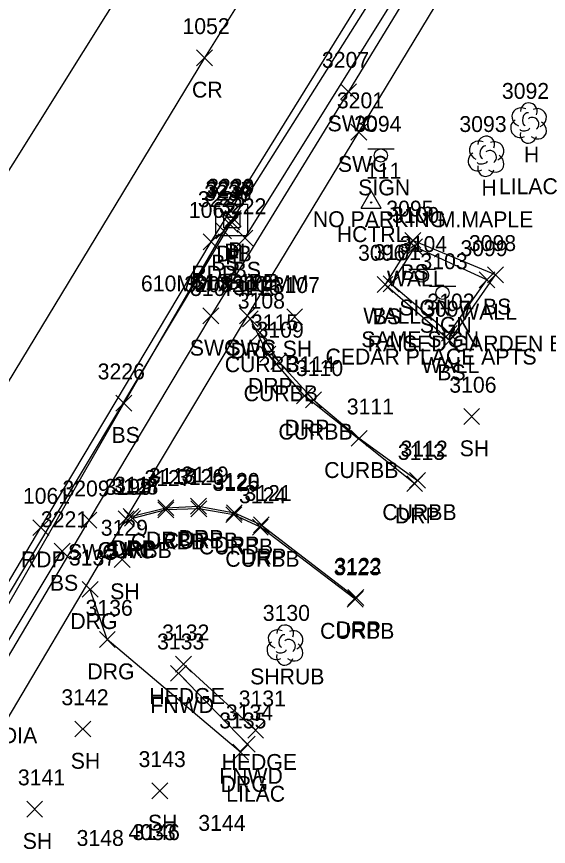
# Model space of a CAD drawing. Extents: x 1634209 to 1639641, y 608564 to 612258.
# Drawn here: x 1638954.2 to 1639021.2, y 610938 to 611042.5 of the extents above; entities that cross this region are included whole.
import ezdxf

# ---------------------------------------------------------------- set-up
doc = ezdxf.new("R2010")
doc.units = 0
for name, color, linetype in [('C_A', 7, 'Continuous'), ('C_I', 7, 'Continuous'), ('CPH', 7, 'Continuous'), ('D_A', 7, 'Continuous'), ('D_C', 7, 'Continuous'), ('D_I', 7, 'Continuous'), ('D_TIC', 7, 'Continuous'), ('DCP', 7, 'Continuous'), ('DS', 7, 'Continuous'), ('L_A', 7, 'Continuous'), ('L_C', 7, 'Continuous'), ('L_I', 7, 'Continuous'), ('L_TIC', 7, 'Continuous'), ('LAHR', 7, 'Continuous'), ('LELB', 7, 'Continuous'), ('LFNC', 7, 'Continuous'), ('LSH', 7, 'Continuous'), ('LTD', 7, 'Continuous'), ('LW', 7, 'Continuous'), ('P_A', 7, 'Continuous'), ('P_I', 7, 'Continuous'), ('P_TIC', 7, 'Continuous'), ('PET', 7, 'Continuous'), ('PRC', 7, 'Continuous'), ('R_A', 7, 'Continuous'), ('R_I', 7, 'Continuous'), ('R_TIC', 7, 'Continuous'), ('RC', 7, 'Continuous'), ('RDG', 7, 'Continuous'), ('RDP', 7, 'Continuous'), ('RSW', 7, 'Continuous'), ('S_A', 7, 'Continuous'), ('S_C', 7, 'Continuous'), ('S_I', 7, 'Continuous'), ('SSGN', 7, 'Continuous'), ('U_C', 7, 'Continuous')]:
    doc.layers.add(name, color=color, linetype=linetype)

msp = doc.modelspace()

# ---------------------------------------------------------------- linework, layer by layer
at = {"layer": 'CPH'}
for p, q in [((1638997.64, 611018.35), (1638998.89, 611020.51)), ((1639000.14, 611018.35), (1638998.89, 611020.51)), ((1638998.89, 611019.07), (1638998.89, 611019.07)), ((1638997.64, 611018.35), (1639000.14, 611018.35))]:
    msp.add_line(p, q, dxfattribs=at)
msp.add_circle((1638998.89, 611019.07), 0.0833, dxfattribs=at)
at = {"layer": 'D_TIC'}
for points in [[(1638980.5, 611016.05), (1638982.5, 611018.05)], [(1638982.5, 611016.05), (1638980.5, 611018.05)], [(1638980.11, 611015.29), (1638982.11, 611017.29)], [(1638982.11, 611015.29), (1638980.11, 611017.29)], [(1638980.28, 611015.63), (1638982.28, 611017.63)], [(1638982.28, 611015.63), (1638980.28, 611017.63)]]:
    msp.add_lwpolyline(points, dxfattribs=at)
at = {"layer": 'DCP'}
for points in [[(1638981.5, 611017.05), (1639053.43, 611130.86)], [(1638930.73, 610932.22), (1638981.11, 611016.29)]]:
    msp.add_lwpolyline(points, dxfattribs=at)
at = {"layer": 'DS'}
for p, q in [((1638979.32, 611018.87), (1638983.32, 611018.87)), ((1638979.32, 611014.87), (1638979.32, 611018.87)), ((1638980.32, 611015.87), (1638980.32, 611017.87)), ((1638980.32, 611017.87), (1638982.32, 611017.87)), ((1638982.32, 611017.87), (1638982.32, 611015.87)), ((1638983.32, 611018.87), (1638983.32, 611014.87)), ((1638981.33, 611016.87), (1638981.33, 611016.87)), ((1638981.33, 611016.87), (1638981.33, 611016.87)), ((1638982.32, 611015.87), (1638980.32, 611015.87)), ((1638983.32, 611014.87), (1638979.32, 611014.87))]:
    msp.add_line(p, q, dxfattribs=at)
at = {"layer": 'L_TIC'}
for points in [[(1638979.31, 611014.48), (1638981.31, 611016.48)], [(1638981.31, 611014.48), (1638979.31, 611016.48)], [(1638981.99, 611013.59), (1638983.99, 611015.59)], [(1638983.99, 611013.59), (1638981.99, 611015.59)], [(1639003.14, 611013.29), (1639005.14, 611015.29)], [(1639005.14, 611013.29), (1639003.14, 611015.29)], [(1639003.38, 611012.49), (1639005.38, 611014.49)], [(1639005.38, 611012.49), (1639003.38, 611014.49)], [(1639013.55, 611008.95), (1639015.55, 611010.95)], [(1639015.55, 611008.95), (1639013.55, 611010.95)], [(1638999.64, 611007.73), (1639001.64, 611009.73)], [(1639001.64, 611007.73), (1638999.64, 611009.73)], [(1639000.42, 611007.81), (1639002.42, 611009.81)], [(1639002.42, 611007.81), (1639000.42, 611009.81)], [(1639012.49, 611008.31), (1639014.49, 611010.31)], [(1639014.49, 611008.31), (1639012.49, 611010.31)], [(1638988.25, 611003.66), (1638990.25, 611005.66)], [(1638990.25, 611003.66), (1638988.25, 611005.66)], [(1639007.74, 611001.59), (1639009.74, 611003.59)], [(1639009.74, 611001.59), (1639007.74, 611003.59)], [(1639007.79, 611000.68), (1639009.79, 611002.68)], [(1639009.79, 611000.68), (1639007.79, 611002.68)], [(1638966.73, 610992.79), (1638968.73, 610994.79)], [(1638968.73, 610992.79), (1638966.73, 610994.79)], [(1639010.56, 610991.11), (1639012.56, 610993.11)], [(1639012.56, 610991.11), (1639010.56, 610993.11)], [(1638958.96, 610974.17), (1638960.96, 610976.17)], [(1638960.96, 610974.17), (1638958.96, 610976.17)], [(1638966.51, 610973.1), (1638968.51, 610975.1)], [(1638968.51, 610973.1), (1638966.51, 610975.1)], [(1638974.24, 610959.92), (1638976.24, 610961.92)], [(1638976.24, 610959.92), (1638974.24, 610961.92)], [(1638973.61, 610958.78), (1638975.61, 610960.78)], [(1638975.61, 610958.78), (1638973.61, 610960.78)], [(1638961.55, 610951.76), (1638963.55, 610953.76)], [(1638963.55, 610951.76), (1638961.55, 610953.76)], [(1638983.33, 610951.61), (1638985.33, 610953.61)], [(1638985.33, 610951.61), (1638983.33, 610953.61)], [(1638982.28, 610949.86), (1638984.28, 610951.86)], [(1638984.28, 610949.86), (1638982.28, 610951.86)], [(1638971.27, 610943.97), (1638973.27, 610945.97)], [(1638973.27, 610943.97), (1638971.27, 610945.97)], [(1638955.49, 610941.67), (1638957.49, 610943.67)], [(1638957.49, 610941.67), (1638955.49, 610943.67)]]:
    msp.add_lwpolyline(points, dxfattribs=at)
at = {"layer": 'LAHR'}
msp.add_lwpolyline([(1638984.33, 610952.61), (1638975.24, 610960.92)], dxfattribs=at)
at = {"layer": 'LELB'}
for points in [[(1638982.99, 611014.59), (1639013.75, 611063.89), (1639039.18, 611103.98)], [(1638980.31, 611015.48), (1638967.73, 610993.79), (1638947.97, 610959.55), (1638931.37, 610930.97), (1638912.43, 610898.55), (1638893.71, 610864.41), (1638879.66, 610839.16)], [(1639004.14, 611014.29), (1639000.64, 611008.73), (1639008.79, 611001.68), (1639014.55, 611009.95)], [(1639014.55, 611009.95), (1639004.14, 611014.29)], [(1638882.82, 610837.01), (1638905.5, 610879.25), (1638921.2, 610907.42), (1638935.13, 610933.84), (1638959.96, 610975.17)]]:
    msp.add_lwpolyline(points, dxfattribs=at)
at = {"layer": 'LFNC'}
msp.add_lwpolyline([(1638974.61, 610959.78), (1638983.28, 610950.86)], dxfattribs=at)
at = {"layer": 'LSH'}
msp.add_line((1638988.01, 610963.38), (1638988.01, 610963.38), dxfattribs=at)
msp.add_line((1638988.01, 610963.38), (1638988.01, 610963.38), dxfattribs=at)
msp.add_arc((1638988.05, 610964.81), 1.05, 335.5272, 180.9563, dxfattribs=at)
for centre, major_axis, ratio, start_param, end_param in [((1638987.21, 610964.05), (1.21, -0.51), 0.895232, 1.570796, 4.712389), ((1638987.8, 610963.84), (-0.208, -0.792), 0.645439, 3.141593, 6.283185), ((1638989.05, 610963.96), (-1.14, -0.48), 0.949671, 1.570796, 4.712389), ((1638986.92, 610962.67), (0.58, -1.04), 0.959034, 3.141593, 6.283185), ((1638988.51, 610963.21), (-0.5, 0.667), 0.989748, 3.141593, 6.283185), ((1638987.55, 610962.63), (-0.625, -0.083), 0.423636, 0, 3.141593), ((1638989.01, 610962.55), (-1.09, 0.79), 0.841452, 1.570796, 4.712389), ((1638988.01, 610961.88), (0.26, 1.06), 0.942809, 1.570796, 4.712389)]:
    msp.add_ellipse(centre, major_axis=major_axis, ratio=ratio, start_param=start_param, end_param=end_param, dxfattribs=at)
at = {"layer": 'LTD'}
for p, q in [((1639018.71, 611029.11), (1639018.71, 611029.11)), ((1639018.71, 611029.11), (1639018.71, 611029.11)), ((1639013.35, 611024.94), (1639013.35, 611024.94)), ((1639013.35, 611024.94), (1639013.35, 611024.94))]:
    msp.add_line(p, q, dxfattribs=at)
for centre in [(1639018.76, 611030.55), (1639013.4, 611026.37)]:
    msp.add_arc(centre, 1.05, 335.5272, 180.9563, dxfattribs=at)
for centre, major_axis, ratio, start_param, end_param in [((1639017.92, 611029.78), (1.21, -0.51), 0.895232, 1.570796, 4.712389), ((1639018.5, 611029.57), (-0.208, -0.792), 0.645439, 3.141593, 6.283185), ((1639019.75, 611029.7), (-1.14, -0.48), 0.949671, 1.570796, 4.712389), ((1639017.63, 611028.41), (0.58, -1.04), 0.959034, 3.141593, 6.283185), ((1639019.21, 611028.95), (-0.5, 0.667), 0.989748, 3.141593, 6.283185), ((1639018.25, 611028.36), (-0.625, -0.083), 0.423636, 0, 3.141593), ((1639019.71, 611028.28), (-1.09, 0.79), 0.841452, 1.570796, 4.712389), ((1639018.71, 611027.61), (0.26, 1.06), 0.942809, 1.570796, 4.712389), ((1639012.56, 611025.6), (1.21, -0.51), 0.895232, 1.570796, 4.712389), ((1639013.14, 611025.39), (-0.208, -0.792), 0.645439, 3.141593, 6.283185), ((1639014.39, 611025.52), (-1.14, -0.48), 0.949671, 1.570796, 4.712389), ((1639012.27, 611024.23), (0.58, -1.04), 0.959034, 3.141593, 6.283185), ((1639013.85, 611024.77), (-0.5, 0.667), 0.989748, 3.141593, 6.283185), ((1639012.89, 611024.19), (-0.625, -0.083), 0.423636, 0, 3.141593), ((1639014.35, 611024.1), (-1.09, 0.79), 0.841452, 1.570796, 4.712389), ((1639013.35, 611023.44), (0.26, 1.06), 0.942809, 1.570796, 4.712389)]:
    msp.add_ellipse(centre, major_axis=major_axis, ratio=ratio, start_param=start_param, end_param=end_param, dxfattribs=at)
at = {"layer": 'LW'}
for points in [[(1639013.49, 611009.31), (1639004.38, 611013.49), (1639001.42, 611008.81), (1639008.74, 611002.59)], [(1639008.74, 611002.59), (1639013.49, 611009.31)]]:
    msp.add_lwpolyline(points, dxfattribs=at)
at = {"layer": 'P_TIC'}
for points in [[(1638976.88, 611036.27), (1638978.88, 611038.27)], [(1638978.88, 611036.27), (1638976.88, 611038.27)], [(1638977.73, 611013.12), (1638979.73, 611015.12)], [(1638979.73, 611013.12), (1638977.73, 611015.12)], [(1638956.25, 610977.12), (1638958.25, 610979.12)], [(1638958.25, 610977.12), (1638956.25, 610979.12)]]:
    msp.add_lwpolyline(points, dxfattribs=at)
at = {"layer": 'PET'}
for points in [[(1638854.83, 610853.22), (1638885.37, 610909), (1638902.82, 610937.28), (1638929.33, 610982.56), (1638950.92, 611019.42), (1638971.29, 611051.92), (1639000.04, 611096.96), (1639023.57, 611133.7), (1639039.12, 611159.19), (1639064.62, 611197.78), (1639080.51, 611223.3), (1639114.23, 611277.34), (1639131.17, 611302.28), (1639149.64, 611331.79), (1639176.42, 611372.35), (1639193.48, 611398.88), (1639220.96, 611441.47), (1639247.22, 611483.75)], [(1638878.4, 610839.82), (1638902.26, 610883.1), (1638925.76, 610925.06), (1638957.25, 610978.12), (1638978.73, 611014.12), (1639004.29, 611055.32), (1639040.97, 611112.28), (1639073.41, 611162.89), (1639072.72, 611163.46), (1639102.57, 611207.56), (1639124.27, 611240.99), (1639140.69, 611264.29), (1639156.2, 611287.4), (1639175.63, 611318.1), (1639189.77, 611341.61), (1639219.88, 611389.38), (1639245.26, 611428.04), (1639265.27, 611462.65)]]:
    msp.add_lwpolyline(points, dxfattribs=at)
at = {"layer": 'PRC'}
msp.add_lwpolyline([(1639250.46, 611462.84), (1639222.36, 611418.18), (1639195.34, 611376.28), (1639169.71, 611336.75), (1639147.17, 611302.78), (1639120.59, 611261.16), (1639092.55, 611217.83), (1639063.71, 611172.41), (1639032.46, 611123.7), (1639004.79, 611080.3), (1638977.88, 611037.27), (1638950.44, 610992.13), (1638925.96, 610950.29), (1638900.29, 610905.36), (1638879.75, 610869.2), (1638867.15, 610846.08)], dxfattribs=at)
at = {"layer": 'R_TIC'}
for points in [[(1638995.03, 611032.02), (1638997.03, 611034.02)], [(1638997.03, 611032.02), (1638995.03, 611034.02)], [(1638996.34, 611026.92), (1638998.34, 611028.92)], [(1638998.34, 611026.92), (1638996.34, 611028.92)], [(1638977.68, 611003.78), (1638979.68, 611005.78)], [(1638979.68, 611003.78), (1638977.68, 611005.78)], [(1638982.29, 611003.79), (1638984.29, 611005.79)], [(1638984.29, 611003.79), (1638982.29, 611005.79)], [(1638982.67, 611003.4), (1638984.67, 611005.4)], [(1638984.67, 611003.4), (1638982.67, 611005.4)], [(1638983.85, 611001.7), (1638985.85, 611003.7)], [(1638985.85, 611001.7), (1638983.85, 611003.7)], [(1638984.86, 610998.97), (1638986.86, 611000.97)], [(1638986.86, 610998.97), (1638984.86, 611000.97)], [(1638986.23, 610998.04), (1638988.23, 611000.04)], [(1638988.23, 610998.04), (1638986.23, 611000.04)], [(1638989.48, 610993.71), (1638991.48, 610995.71)], [(1638991.48, 610993.71), (1638989.48, 610995.71)], [(1638990.62, 610993.21), (1638992.62, 610995.21)], [(1638992.62, 610993.21), (1638990.62, 610995.21)], [(1638996.38, 610988.37), (1638998.38, 610990.37)], [(1638998.38, 610988.37), (1638996.38, 610990.37)], [(1639003.38, 610982.65), (1639005.38, 610984.65)], [(1639005.38, 610982.65), (1639003.38, 610984.65)], [(1639003.72, 610983.07), (1639005.72, 610985.07)], [(1639005.72, 610983.07), (1639003.72, 610985.07)], [(1638972.01, 610979.63), (1638974.01, 610981.63)], [(1638974.01, 610979.63), (1638972.01, 610981.63)], [(1638972.01, 610979.37), (1638974.01, 610981.37)], [(1638974.01, 610979.37), (1638972.01, 610981.37)], [(1638976.13, 610979.81), (1638978.13, 610981.81)], [(1638978.13, 610979.81), (1638976.13, 610981.81)], [(1638976.17, 610979.5), (1638978.17, 610981.5)], [(1638978.17, 610979.5), (1638976.17, 610981.5)], [(1638967.01, 610978.25), (1638969.01, 610980.25)], [(1638969.01, 610978.25), (1638967.01, 610980.25)], [(1638967.62, 610978.53), (1638969.62, 610980.53)], [(1638969.62, 610978.53), (1638967.62, 610980.53)], [(1638967.82, 610978.29), (1638969.82, 610980.29)], [(1638969.82, 610978.29), (1638967.82, 610980.29)], [(1638980.59, 610978.75), (1638982.59, 610980.75)], [(1638982.59, 610978.75), (1638980.59, 610980.75)], [(1638980.65, 610979), (1638982.65, 610981)], [(1638982.65, 610979), (1638980.65, 610981)], [(1638962.33, 610978.05), (1638964.33, 610980.05)], [(1638964.33, 610978.05), (1638962.33, 610980.05)], [(1638984.05, 610977.48), (1638986.05, 610979.48)], [(1638986.05, 610977.48), (1638984.05, 610979.48)], [(1638983.93, 610977.19), (1638985.93, 610979.19)], [(1638985.93, 610977.19), (1638983.93, 610979.19)], [(1638962.49, 610969.35), (1638964.49, 610971.35)], [(1638964.49, 610969.35), (1638962.49, 610971.35)], [(1638995.87, 610968.12), (1638997.87, 610970.12)], [(1638997.87, 610968.12), (1638995.87, 610970.12)], [(1638995.96, 610968.31), (1638997.96, 610970.31)], [(1638997.96, 610968.31), (1638995.96, 610970.31)], [(1638964.64, 610963.02), (1638966.64, 610965.02)], [(1638966.64, 610963.02), (1638964.64, 610965.02)], [(1638981.44, 610948.84), (1638983.44, 610950.84)], [(1638983.44, 610948.84), (1638981.44, 610950.84)]]:
    msp.add_lwpolyline(points, dxfattribs=at)
at = {"layer": 'RC'}
for points in [[(1638984.85, 611002.7), (1638987.23, 610999.04), (1638991.62, 610994.21), (1638997.38, 610989.37), (1639004.72, 610984.07)], [(1638996.87, 610969.12), (1638984.93, 610978.19), (1638981.59, 610979.75), (1638977.17, 610980.5), (1638973.01, 610980.37), (1638968.82, 610979.29)]]:
    msp.add_lwpolyline(points, dxfattribs=at)
at = {"layer": 'RDG'}
msp.add_lwpolyline([(1638982.44, 610949.84), (1638965.64, 610964.02), (1638963.49, 610970.35)], dxfattribs=at)
at = {"layer": 'RDP'}
for points in [[(1639004.38, 610983.65), (1638990.48, 610994.71), (1638985.86, 610999.97), (1638983.67, 611004.4)], [(1638968.62, 610979.53), (1638973.01, 610980.63), (1638977.13, 610980.81), (1638981.65, 610980), (1638985.05, 610978.48), (1638996.96, 610969.31)]]:
    msp.add_lwpolyline(points, dxfattribs=at)
at = {"layer": 'RSW'}
for points in [[(1639042.52, 611106.87), (1639016.95, 611067.31), (1638996.03, 611033.02), (1638978.68, 611004.78), (1638963.33, 610979.05), (1638946.23, 610950.27), (1638931.64, 610924.09), (1638919.4, 610902.22), (1638904.83, 610875.98), (1638895.3, 610858.44), (1638883.54, 610836.57)], [(1638887.24, 610836.54), (1638902.8, 610864.3), (1638908.08, 610874.62), (1638910.81, 610879.12), (1638923.92, 610902.1), (1638938.05, 610928.02), (1638949.86, 610948.73), (1638968.01, 610979.25), (1638983.29, 611004.79), (1638997.34, 611027.92), (1639015.73, 611058.3), (1639044.74, 611103.21)]]:
    msp.add_lwpolyline(points, dxfattribs=at)
at = {"layer": 'SSGN'}
for p, q in [((1638998.47, 611025.82), (1639001.8, 611025.82)), ((1639000.12, 611024.98), (1639000.12, 611024.98)), ((1639003.66, 611010.68), (1639006.99, 611010.68)), ((1639005.3, 611009.85), (1639005.3, 611009.85)), ((1639006.24, 611008.52), (1639009.57, 611008.52)), ((1639007.89, 611007.68), (1639007.89, 611007.68))]:
    msp.add_line(p, q, dxfattribs=at)
for centre in [(1639000.12, 611024.98), (1639005.3, 611009.85), (1639007.89, 611007.68)]:
    msp.add_circle(centre, 0.833, dxfattribs=at)

# ---------------------------------------------------------------- texts
at = {"layer": 'C_A'}
msp.add_text('HCTRL', height=2, dxfattribs=at).set_placement((1638994.56, 611014.07))
at = {"layer": 'C_I'}
for s, p in [('111', (1638998.23, 611022.07)), ('4033', (1638968.31, 610938.77))]:
    msp.add_text(s, height=2, dxfattribs=at).set_placement(p)
at = {"layer": 'D_A'}
for s, p in [('DI', (1638980.38, 611011.87)), ('P', (1638980.88, 611012.05)), ('DIB', (1638979.38, 611011.63)), ('P', (1638980.49, 611011.29))]:
    msp.add_text(s, height=2, dxfattribs=at).set_placement(p)
at = {"layer": 'D_C'}
for s, p in [('610MM X 610MM', (1638969.88, 611007.87)), ('310PIPE', (1638976.46, 611008.05)), ('310PIPE', (1638976.07, 611007.29))]:
    msp.add_text(s, height=2, dxfattribs=at).set_placement(p)
at = {"layer": 'D_I'}
for s, p in [('3239', (1638978.23, 611020.05)), ('3238', (1638977.85, 611019.29)), ('3236', (1638978.01, 611019.87)), ('3237', (1638978.02, 611019.63))]:
    msp.add_text(s, height=2, dxfattribs=at).set_placement(p)
at = {"layer": 'L_A'}
for s, p in [('H', (1639018.14, 611024.11)), ('H', (1639012.79, 611019.94)), ('BS', (1638978.75, 611010.48)), ('BS', (1638981.43, 611009.59)), ('BS', (1639002.58, 611009.29)), ('WALL', (1639000.87, 611008.49)), ('BS', (1639012.99, 611004.95)), ('WALL', (1638997.9, 611003.81)), ('BS', (1638999.08, 611003.73)), ('WALL', (1639009.98, 611004.31)), ('SH', (1638987.74, 610999.66)), ('WALL', (1639005.23, 610997.59)), ('BS', (1639007.23, 610996.68)), ('BS', (1638966.17, 610988.79)), ('SH', (1639010.05, 610987.11)), ('BS', (1638958.4, 610970.17)), ('SH', (1638966, 610969.1)), ('SHRUB', (1638983.64, 610958.38)), ('HEDGE', (1638970.94, 610955.92)), ('FNWD', (1638971.07, 610954.78)), ('SH', (1638961.03, 610947.76)), ('HEDGE', (1638980.03, 610947.61)), ('FNWD', (1638979.74, 610945.86)), ('SH', (1638970.76, 610939.97)), ('SH', (1638954.98, 610937.67))]:
    msp.add_text(s, height=2, dxfattribs=at).set_placement(p)
at = {"layer": 'L_C'}
for s, p in [('LILAC', (1639014.98, 611020.11)), ('M.MAPLE', (1639007.29, 611015.94)), ('RAISED GARDEN BED', (1638998.44, 611000.31)), ('LILAC', (1638980.61, 610943.61))]:
    msp.add_text(s, height=2, dxfattribs=at).set_placement(p)
at = {"layer": 'L_I'}
for s, p in [('3092', (1639015.37, 611032.11)), ('3093', (1639010.01, 611027.94)), ('3225', (1638977.05, 611018.48)), ('3222', (1638979.73, 611017.59)), ('3095', (1639000.8, 611017.29)), ('3100', (1639001.52, 611016.49)), ('3098', (1639011.21, 611012.95)), ('3096', (1638997.24, 611011.73)), ('3101', (1638999.21, 611011.81)), ('3099', (1639010.14, 611012.31)), ('3107', (1638986.48, 611007.66)), ('3102', (1639005.97, 611005.59)), ('3097', (1639005.45, 611004.68)), ('3226', (1638964.42, 610996.79)), ('3106', (1639008.74, 610995.11)), ('3221', (1638957.27, 610978.17)), ('3129', (1638964.81, 610977.1)), ('3130', (1638985.23, 610966.38)), ('3132', (1638972.55, 610963.92)), ('3133', (1638971.91, 610962.78)), ('3142', (1638959.85, 610955.76)), ('3131', (1638982.2, 610955.61)), ('3134', (1638980.58, 610953.86)), ('3143', (1638969.58, 610947.97)), ('3141', (1638954.37, 610945.67)), ('3144', (1638977.11, 610939.94)), ('3146', (1638968.83, 610938.78)), ('3148', (1638961.77, 610938.04))]:
    msp.add_text(s, height=2, dxfattribs=at).set_placement(p)
at = {"layer": 'P_A'}
for s, p in [('CR', (1638976.31, 611032.27)), ('RDP', (1638976.22, 611009.12)), ('RDP', (1638954.74, 610973.12))]:
    msp.add_text(s, height=2, dxfattribs=at).set_placement(p)
at = {"layer": 'P_I'}
for s, p in [('1052', (1638975.11, 611040.27)), ('1062', (1638975.91, 611017.12)), ('1061', (1638955, 610981.12))]:
    msp.add_text(s, height=2, dxfattribs=at).set_placement(p)
at = {"layer": 'R_A'}
for s, p in [('SWC', (1638993.4, 611028.02)), ('SWC', (1638994.7, 611022.92)), ('SWC', (1638976.04, 610999.78)), ('SWC', (1638980.65, 610999.79)), ('DRP', (1638981.16, 610999.4)), ('CURBB', (1638980.44, 610997.7)), ('DRP', (1638983.35, 610994.97)), ('CURBB', (1638982.82, 610994.04)), ('CURBB', (1638987.2, 610989.21)), ('DRP', (1638987.97, 610989.71)), ('CURBB', (1638992.97, 610984.37)), ('CURBB', (1639000.3, 610979.07)), ('DRP', (1639001.87, 610978.65)), ('CURBB', (1638968.59, 610975.37)), ('DRP', (1638970.5, 610975.63)), ('CURBB', (1638972.75, 610975.5)), ('DRP', (1638974.61, 610975.81)), ('SWC', (1638960.69, 610974.05)), ('CURBB', (1638964.41, 610974.29)), ('SWC', (1638965.37, 610974.25)), ('DRP', (1638966.11, 610974.53)), ('CURBB', (1638977.17, 610974.75)), ('DRP', (1638979.14, 610975)), ('CURBB', (1638980.51, 610973.19)), ('DRP', (1638982.54, 610973.48)), ('DRG', (1638960.98, 610965.35)), ('CURBB', (1638992.45, 610964.12)), ('DRP', (1638994.45, 610964.31)), ('DRG', (1638963.13, 610959.02)), ('DRG', (1638979.92, 610944.84))]:
    msp.add_text(s, height=2, dxfattribs=at).set_placement(p)
at = {"layer": 'R_I'}
for s, p in [('3207', (1638992.69, 611036.02)), ('3201', (1638994.57, 611030.92)), ('3208', (1638975.34, 611007.78)), ('3200', (1638979.86, 611007.79)), ('3116', (1638981.49, 611007.4)), ('3108', (1638982.08, 611005.7)), ('3115', (1638983.74, 611002.97)), ('3109', (1638984.45, 611002.04)), ('3114', (1638988.36, 610997.71)), ('3110', (1638989.41, 610997.21)), ('3111', (1638995.82, 610992.37)), ('3113', (1639002.25, 610986.65)), ('3112', (1639002.59, 610987.07)), ('3118', (1638970.88, 610983.63)), ('3126', (1638974.42, 610983.5)), ('3119', (1638974.99, 610983.81)), ('3117', (1638966.49, 610982.53)), ('3127', (1638970.32, 610983.37)), ('3120', (1638978.87, 610983)), ('3125', (1638978.9, 610982.75)), ('3209', (1638959.98, 610982.05)), ('3199', (1638965.31, 610982.25)), ('3128', (1638966.13, 610982.29)), ('3121', (1638982.92, 610981.48)), ('3124', (1638982.24, 610981.19)), ('3137', (1638960.8, 610973.35)), ('3123', (1638994.17, 610972.12)), ('3122', (1638994.27, 610972.31)), ('3136', (1638962.9, 610967.02)), ('3135', (1638979.74, 610952.84))]:
    msp.add_text(s, height=2, dxfattribs=at).set_placement(p)
at = {"layer": 'S_A'}
for p in [(1638997.26, 611019.96), (1639002.44, 611004.83), (1639005.03, 611002.66)]:
    msp.add_text('SIGN', height=2, dxfattribs=at).set_placement(p)
at = {"layer": 'S_C'}
for s, p in [('NO PARKING', (1638991.54, 611015.96)), ('SAME SIGN', (1638997.65, 611000.83)), ('CEDAR PLACE APTS', (1638993.14, 610998.66))]:
    msp.add_text(s, height=2, dxfattribs=at).set_placement(p)
at = {"layer": 'S_I'}
for s, p in [('3094', (1638996.76, 611027.96)), ('3104', (1639002.51, 611012.83)), ('3103', (1639005.1, 611010.66))]:
    msp.add_text(s, height=2, dxfattribs=at).set_placement(p)
at = {"layer": 'U_C'}
msp.add_text('660MM DIA', height=2, dxfattribs=at).set_placement((1638942.69, 610950.96))

doc.saveas('drawing.dxf')
